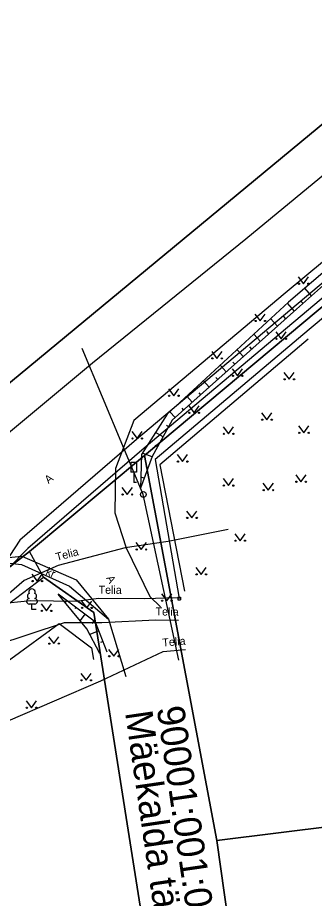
# Model space of a CAD drawing. Extents: x 648017 to 648227, y 6561313 to 6561610.
# Drawn here: x 648068.3 to 648094.3, y 6561381.6 to 6561458.6 of the extents above; entities that cross this region are included whole.
import ezdxf

# ---------------------------------------------------------------- set-up
doc = ezdxf.new("R2010")
doc.units = 0
for name, color, linetype in [('AED', 7, 'Continuous'), ('HALJASTUS', 7, 'Continuous'), ('KASUTUSALA', 7, 'Continuous'), ('LIIKLUS', 7, 'Continuous'), ('MPOHULIIN', 7, 'Continuous'), ('PIIR', 7, 'Continuous'), ('POST', 7, 'Continuous'), ('PR_SIDE', 7, 'Continuous'), ('PUU', 7, 'Continuous'), ('RELJEEF', 7, 'Continuous'), ('SITRASS', 7, 'Continuous'), ('TEE', 7, 'Continuous')]:
    doc.layers.add(name, color=color, linetype=linetype)

msp = doc.modelspace()

# ---------------------------------------------------------------- linework, layer by layer
at = {"layer": 'AED'}
for p, q in [((648082.32, 6561407.963), (648082.32, 6561407.713)), ((648082.32, 6561407.963), (648082.57, 6561407.963)), ((648082.57, 6561407.963), (648082.57, 6561407.713)), ((648082.32, 6561407.713), (648082.57, 6561407.713))]:
    msp.add_line(p, q, dxfattribs=at)
msp.add_lwpolyline([(648111.122, 6561445.808), (648093.833, 6561431.357), (648080.35, 6561420.002), (648082.445, 6561407.838)], dxfattribs=at)
at = {"layer": 'HALJASTUS'}
for p, q in [((648092.866, 6561435.975), (648093.33, 6561435.369)), ((648093.33, 6561435.369), (648093.775, 6561435.975)), ((648089.073, 6561432.718), (648089.537, 6561432.111)), ((648089.537, 6561432.111), (648089.982, 6561432.718)), ((648090.905, 6561431.157), (648091.368, 6561430.55)), ((648091.368, 6561430.55), (648091.814, 6561431.157)), ((648085.29, 6561429.449), (648085.753, 6561428.842)), ((648085.753, 6561428.842), (648086.199, 6561429.449)), ((648087.092, 6561427.922), (648087.556, 6561427.315)), ((648087.556, 6561427.315), (648088.001, 6561427.922)), ((648091.615, 6561427.617), (648092.079, 6561427.011)), ((648092.079, 6561427.011), (648092.524, 6561427.617)), ((648081.506, 6561426.18), (648081.969, 6561425.574)), ((648081.969, 6561425.574), (648082.415, 6561426.18)), ((648083.28, 6561424.687), (648083.743, 6561424.081)), ((648083.743, 6561424.081), (648084.189, 6561424.687)), ((648089.658, 6561424.086), (648090.121, 6561423.48)), ((648090.121, 6561423.48), (648090.567, 6561424.086)), ((648086.298, 6561422.844), (648086.761, 6561422.237)), ((648086.761, 6561422.237), (648087.207, 6561422.844)), ((648092.898, 6561422.935), (648093.362, 6561422.328)), ((648093.362, 6561422.328), (648093.807, 6561422.935)), ((648078.298, 6561422.441), (648078.761, 6561421.834)), ((648078.761, 6561421.834), (648079.207, 6561422.441)), ((648082.274, 6561420.423), (648082.738, 6561419.816)), ((648082.738, 6561419.816), (648083.183, 6561420.423)), ((648086.296, 6561418.322), (648086.759, 6561417.715)), ((648086.759, 6561417.715), (648087.205, 6561418.322)), ((648089.784, 6561417.924), (648090.247, 6561417.318)), ((648090.247, 6561417.318), (648090.693, 6561417.924)), ((648092.648, 6561418.654), (648093.111, 6561418.048)), ((648093.111, 6561418.048), (648093.557, 6561418.654)), ((648077.433, 6561417.542), (648077.896, 6561416.935)), ((648077.896, 6561416.935), (648078.342, 6561417.542)), ((648083.092, 6561415.49), (648083.555, 6561414.884)), ((648083.555, 6561414.884), (648084.001, 6561415.49)), ((648087.319, 6561413.5), (648087.782, 6561412.894)), ((648087.782, 6561412.894), (648088.228, 6561413.5)), ((648078.661, 6561412.73), (648079.124, 6561412.123)), ((648079.124, 6561412.123), (648079.57, 6561412.73)), ((648083.909, 6561410.558), (648084.372, 6561409.951)), ((648084.372, 6561409.951), (648084.818, 6561410.558)), ((648069.546, 6561409.97), (648070.01, 6561409.364)), ((648070.01, 6561409.364), (648070.455, 6561409.97)), ((648080.889, 6561408.254), (648081.353, 6561407.647)), ((648081.353, 6561407.647), (648081.798, 6561408.254)), ((648070.353, 6561407.36), (648070.816, 6561406.753)), ((648070.816, 6561406.753), (648071.262, 6561407.36)), ((648073.881, 6561407.619), (648074.345, 6561407.013)), ((648074.345, 6561407.013), (648074.79, 6561407.619)), ((648071.009, 6561404.497), (648071.472, 6561403.89)), ((648071.472, 6561403.89), (648071.918, 6561404.497)), ((648076.257, 6561403.389), (648076.72, 6561402.783)), ((648076.72, 6561402.783), (648077.166, 6561403.389)), ((648073.83, 6561401.287), (648074.293, 6561400.68)), ((648074.293, 6561400.68), (648074.739, 6561401.287)), ((648069.037, 6561398.889), (648069.5, 6561398.282)), ((648069.5, 6561398.282), (648069.946, 6561398.889))]:
    msp.add_line(p, q, dxfattribs=at)
for points in [[(648093.746, 6561430.532), (648080.736, 6561419.534), (648082.92, 6561408.479)], [(648043.318, 6561383.328), (648045.146, 6561384.984), (648050.259, 6561388.844), (648067.703, 6561402.558), (648071.941, 6561405.665), (648074.773, 6561403.529), (648074.941, 6561402.506)]]:
    msp.add_lwpolyline(points, dxfattribs=at)
for centre in [(648092.929, 6561435.369), (648093.757, 6561435.369), (648089.136, 6561432.111), (648089.964, 6561432.111), (648090.967, 6561430.55), (648091.796, 6561430.55), (648085.352, 6561428.842), (648086.181, 6561428.842), (648087.155, 6561427.315), (648087.983, 6561427.315), (648091.678, 6561427.011), (648092.506, 6561427.011), (648081.568, 6561425.574), (648082.397, 6561425.574), (648083.342, 6561424.081), (648084.171, 6561424.081), (648089.72, 6561423.48), (648090.549, 6561423.48), (648078.36, 6561421.834), (648079.189, 6561421.834), (648086.36, 6561422.237), (648087.189, 6561422.237), (648092.961, 6561422.328), (648093.79, 6561422.328), (648082.337, 6561419.816), (648083.165, 6561419.816), (648092.71, 6561418.048), (648093.539, 6561418.048), (648086.358, 6561417.715), (648087.187, 6561417.715), (648089.846, 6561417.318), (648090.675, 6561417.318), (648077.495, 6561416.935), (648078.324, 6561416.935), (648083.154, 6561414.884), (648083.983, 6561414.884), (648087.381, 6561412.894), (648088.21, 6561412.894), (648078.723, 6561412.123), (648079.552, 6561412.123), (648083.971, 6561409.951), (648084.8, 6561409.951), (648069.609, 6561409.364), (648070.437, 6561409.364), (648080.951, 6561407.647), (648081.78, 6561407.647), (648070.415, 6561406.753), (648071.244, 6561406.753), (648073.944, 6561407.013), (648074.773, 6561407.013), (648071.071, 6561403.89), (648071.9, 6561403.89), (648076.319, 6561402.783), (648077.148, 6561402.783), (648073.892, 6561400.68), (648074.721, 6561400.68), (648069.099, 6561398.282), (648069.928, 6561398.282)]:
    msp.add_circle(centre, 0.055, dxfattribs=at)
at = {"layer": 'KASUTUSALA'}
msp.add_lwpolyline([(648069.33, 6561411.95), (648079.41, 6561420.36), (648130.76, 6561463.29), (648148.46, 6561478.24), (648152.687, 6561481.861), (648163.17, 6561490.84), (648165.149, 6561492.835), (648178.343, 6561506.54), (648179.793, 6561507.812), (648180.15, 6561508.27), (648181.07, 6561509.57), (648179.717, 6561510.405), (648176.961, 6561507.989), (648163.749, 6561494.265), (648163.1, 6561493.666), (648154.204, 6561485.901), (648141.111, 6561474.192), (648118.068, 6561454.823), (648078.72, 6561421.738), (648068.502, 6561412.945), (648066.261, 6561409.593)], close=True, dxfattribs=at)
at = {"layer": 'LIIKLUS'}
for p, q in [((648078.214, 6561419.738), (648078.214, 6561418.888)), ((648078.714, 6561419.738), (648078.214, 6561419.738)), ((648078.714, 6561419.738), (648078.714, 6561418.888)), ((648078.714, 6561418.888), (648078.214, 6561418.888)), ((648078.464, 6561418.888), (648078.464, 6561417.988)), ((648078.714, 6561417.988), (648078.464, 6561417.988))]:
    msp.add_line(p, q, dxfattribs=at)
at = {"layer": 'MPOHULIIN'}
msp.add_lwpolyline([(648082.404, 6561402.438), (648079.305, 6561416.941), (648073.956, 6561429.718)], dxfattribs=at)
at = {"layer": 'PIIR'}
for points in [[(648199.342, 6561559.885), (648199.07, 6561558.2), (648195.16, 6561543.45), (648190.37, 6561530.46), (648184.89, 6561519.28), (648179.37, 6561510.62), (648181.07, 6561509.57), (648180.15, 6561508.27), (648175.42, 6561502.2), (648170.88, 6561497.65), (648163.17, 6561490.84), (648148.46, 6561478.24), (648130.76, 6561463.29), (648079.41, 6561420.36), (648069.33, 6561411.95), (648039.275, 6561388.867)], [(648148.783, 6561559.885), (648090, 6561513.15), (648123.09, 6561472.56), (648039.275, 6561403.329)], [(648039.275, 6561403.329), (648123.09, 6561472.56), (648162.4, 6561506.57), (648170.84, 6561515.84), (648172.53, 6561514.72), (648177.65, 6561522.71), (648182.83, 6561533.2), (648187.47, 6561545.71), (648191.21, 6561559.62), (648191.239, 6561559.885)], [(648083.938, 6561349.885), (648074.96, 6561406.62), (648070.56, 6561409.69), (648069.33, 6561411.95), (648079.41, 6561420.36), (648085.73, 6561386.66), (648090.928, 6561349.885)], [(648039.275, 6561385.901), (648070.56, 6561409.69), (648074.96, 6561406.62), (648083.938, 6561349.885)], [(648090.928, 6561349.885), (648085.73, 6561386.66), (648122.86, 6561391.28), (648128.277, 6561349.885)]]:
    msp.add_lwpolyline(points, dxfattribs=at)
msp.add_lwpolyline([(648079.41, 6561420.36), (648130.76, 6561463.29), (648138.52, 6561393.32), (648122.86, 6561391.28), (648085.73, 6561386.66)], close=True, dxfattribs=at)
at = {"layer": 'POST'}
msp.add_circle((648079.305, 6561416.941), 0.25, dxfattribs=at)
at = {"layer": 'PR_SIDE'}
msp.add_lwpolyline([(648199.292, 6561518.475), (648197.479, 6561519.53), (648193.724, 6561520.506), (648191.997, 6561519.841), (648177.652, 6561507.265), (648164.449, 6561493.55), (648163.768, 6561492.922), (648154.867, 6561485.151), (648141.766, 6561473.436), (648118.712, 6561454.058), (648079.383, 6561420.989), (648069.186, 6561412.213), (648060.526, 6561403.421), (648044.656, 6561390.621), (648039.275, 6561386.529)], dxfattribs=at)
at = {"layer": 'PUU'}
for p, q in [((648069.794, 6561407.35), (648069.314, 6561407.35)), ((648069.554, 6561406.875), (648069.554, 6561407.35)), ((648069.934, 6561406.875), (648069.554, 6561406.875))]:
    msp.add_line(p, q, dxfattribs=at)
for centre, radius, start, end in [((648069.554, 6561408.395), 0.277, 332.5799, 207.4201), ((648069.384, 6561408.048), 0.233, 109.02174, 253.14154), ((648069.724, 6561408.048), 0.233, 286.85082, 70.98591), ((648069.316, 6561407.588), 0.238, 90.0016, 269.3953), ((648069.791, 6561407.588), 0.238, 270.6047, 89.9984)]:
    msp.add_arc(centre, radius, start, end, dxfattribs=at)
at = {"layer": 'RELJEEF'}
for p, q in [((648094.04, 6561434.305), (648093.444, 6561434.976)), ((648092.546, 6561432.976), (648091.925, 6561433.672)), ((648093.293, 6561433.64), (648093.11, 6561433.846)), ((648091.052, 6561431.646), (648090.455, 6561432.316)), ((648091.799, 6561432.311), (648091.616, 6561432.516)), ((648090.305, 6561430.981), (648090.129, 6561431.178)), ((648089.558, 6561430.316), (648088.985, 6561430.96)), ((648088.064, 6561428.986), (648087.515, 6561429.603)), ((648088.811, 6561429.651), (648088.643, 6561429.84)), ((648086.57, 6561427.656), (648086.044, 6561428.247)), ((648087.317, 6561428.321), (648087.156, 6561428.502)), ((648085.823, 6561426.991), (648085.669, 6561427.165)), ((648085.076, 6561426.326), (648084.574, 6561426.891)), ((648084.33, 6561425.661), (648084.182, 6561425.827)), ((648083.583, 6561424.997), (648083.104, 6561425.534)), ((648082.089, 6561423.667), (648081.634, 6561424.178)), ((648082.836, 6561424.332), (648082.696, 6561424.489)), ((648081.512, 6561422.866), (648081.332, 6561422.965)), ((648081.03, 6561421.99), (648080.374, 6561422.351)), ((648080.548, 6561421.114), (648080.334, 6561421.231)), ((648080.07, 6561420.236), (648079.225, 6561420.545)), ((648079.726, 6561419.297), (648079.546, 6561419.363)), ((648079.382, 6561418.358), (648079.092, 6561418.464)), ((648072.58, 6561407.675), (648072.447, 6561407.497)), ((648073.38, 6561407.075), (648073.297, 6561406.964)), ((648074.18, 6561406.475), (648073.76, 6561405.914)), ((648074.981, 6561405.876), (648074.808, 6561405.645)), ((648075.415, 6561404.999), (648074.62, 6561404.692)), ((648075.776, 6561404.067), (648075.568, 6561403.987))]:
    msp.add_line(p, q, dxfattribs=at)
for points in [[(648105.657, 6561445.249), (648104.268, 6561443.398), (648092.722, 6561433.133), (648081.823, 6561423.43), (648080.08, 6561420.264), (648079.06, 6561417.48)], [(648105.657, 6561445.249), (648103.887, 6561443.894), (648092.031, 6561433.769), (648081.397, 6561423.96), (648079.154, 6561420.435), (648079.06, 6561417.48)], [(648076.136, 6561403.134), (648075.117, 6561405.774), (648071.841, 6561408.228)], [(648075.485, 6561403.035), (648074.361, 6561405.189), (648071.841, 6561408.228)]]:
    msp.add_lwpolyline(points, dxfattribs=at)
at = {"layer": 'SITRASS'}
for points in [[(648086.748, 6561413.866), (648081.478, 6561412.832), (648077.7, 6561412.27), (648071.841, 6561410.71), (648068.859, 6561409.424), (648066.455, 6561407.341), (648064.964, 6561406.234), (648059.947, 6561402.189), (648054.198, 6561397.472), (648045.438, 6561390.103), (648040.817, 6561386.172), (648039.275, 6561384.639)], [(648082.302, 6561407.901), (648079.4, 6561407.797), (648075.375, 6561407.837), (648073.437, 6561407.588), (648069.464, 6561407.638), (648066.527, 6561407.339), (648064.664, 6561407.213), (648062.936, 6561406.667), (648062.868, 6561406.65), (648058.98, 6561403.232), (648053.259, 6561398.322), (648044.21, 6561391.764), (648039.275, 6561387.907)], [(648082.387, 6561405.903), (648080.358, 6561405.942), (648075.684, 6561405.704), (648072.377, 6561405.712), (648066.229, 6561403.712), (648060.686, 6561401.017), (648054.729, 6561396.422), (648045.992, 6561389.333), (648040.723, 6561385.425), (648039.275, 6561384.147)], [(648039.275, 6561382.438), (648041.726, 6561384.362), (648047.054, 6561387.491), (648056.131, 6561391.983), (648067.468, 6561397.134), (648075.572, 6561400.639), (648081.037, 6561403.206), (648083.002, 6561403.37)]]:
    msp.add_lwpolyline(points, dxfattribs=at)
at = {"layer": 'TEE'}
for points in [[(648190.847, 6561503.014), (648190.795, 6561505.329), (648190.473, 6561508.69), (648186.913, 6561508.391), (648184.052, 6561507.669), (648178.235, 6561505.797), (648172.597, 6561503.638), (648169.601, 6561500.659), (648161.13, 6561493.277), (648153.241, 6561486.387), (648142.295, 6561477.024), (648134.213, 6561470.18), (648127.303, 6561464.531), (648121.652, 6561459.668), (648108.949, 6561448.834), (648091.715, 6561434.542), (648078.474, 6561423.42), (648076.859, 6561419.217), (648076.802, 6561415.34), (648077.814, 6561412.283), (648079.886, 6561408.026), (648080.807, 6561407.116)], [(648123.326, 6561469.198), (648122.878, 6561468.198), (648118.137, 6561464.111), (648105.565, 6561453.509), (648088.284, 6561439.263), (648074.857, 6561428.431), (648059.756, 6561415.877), (648040.748, 6561400.235), (648039.275, 6561399.135)], [(648039.275, 6561392.3), (648044.53, 6561396.273), (648062.926, 6561410.785), (648065.147, 6561411.205), (648068.657, 6561411.551), (648073.418, 6561409.482), (648076.263, 6561406.029), (648077.76, 6561401.016)], [(648039.275, 6561391.609), (648044.873, 6561395.803), (648063.173, 6561410.375), (648065.147, 6561411.205), (648068.648, 6561410.798), (648072.831, 6561408.913), (648076.263, 6561406.029)]]:
    msp.add_lwpolyline(points, dxfattribs=at)

# ---------------------------------------------------------------- texts
at = {"layer": 'PIIR'}
for s, p in [('Mäekalda tänav L1', (648077.7, 6561397.874)), ('90001:001:0388', (648080.47, 6561398.278))]:
    msp.add_text(s, height=2.4, rotation=278.30431, dxfattribs=at).set_placement(p)
at = {"layer": 'SITRASS'}
for rotation, p in [(14.86832, (648071.734, 6561411.116)), (359.37933, (648075.38, 6561408.257)), (358.83644, (648080.366, 6561406.362)), (4.72091, (648081.003, 6561403.625))]:
    msp.add_text('Telia', height=0.7, rotation=rotation, dxfattribs=at).set_placement(p)
at = {"layer": 'TEE'}
for s, rotation, p in [('A', 38.63166, (648070.999, 6561417.845)), ('kr', 335.68859, (648070.701, 6561409.95)), ('A', 298.46892, (648076.033, 6561409.63))]:
    msp.add_text(s, height=0.7, rotation=rotation, dxfattribs=at).set_placement(p)

doc.saveas('drawing.dxf')
